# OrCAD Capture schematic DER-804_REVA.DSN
size Custom; title: DER-804; rev: RevA
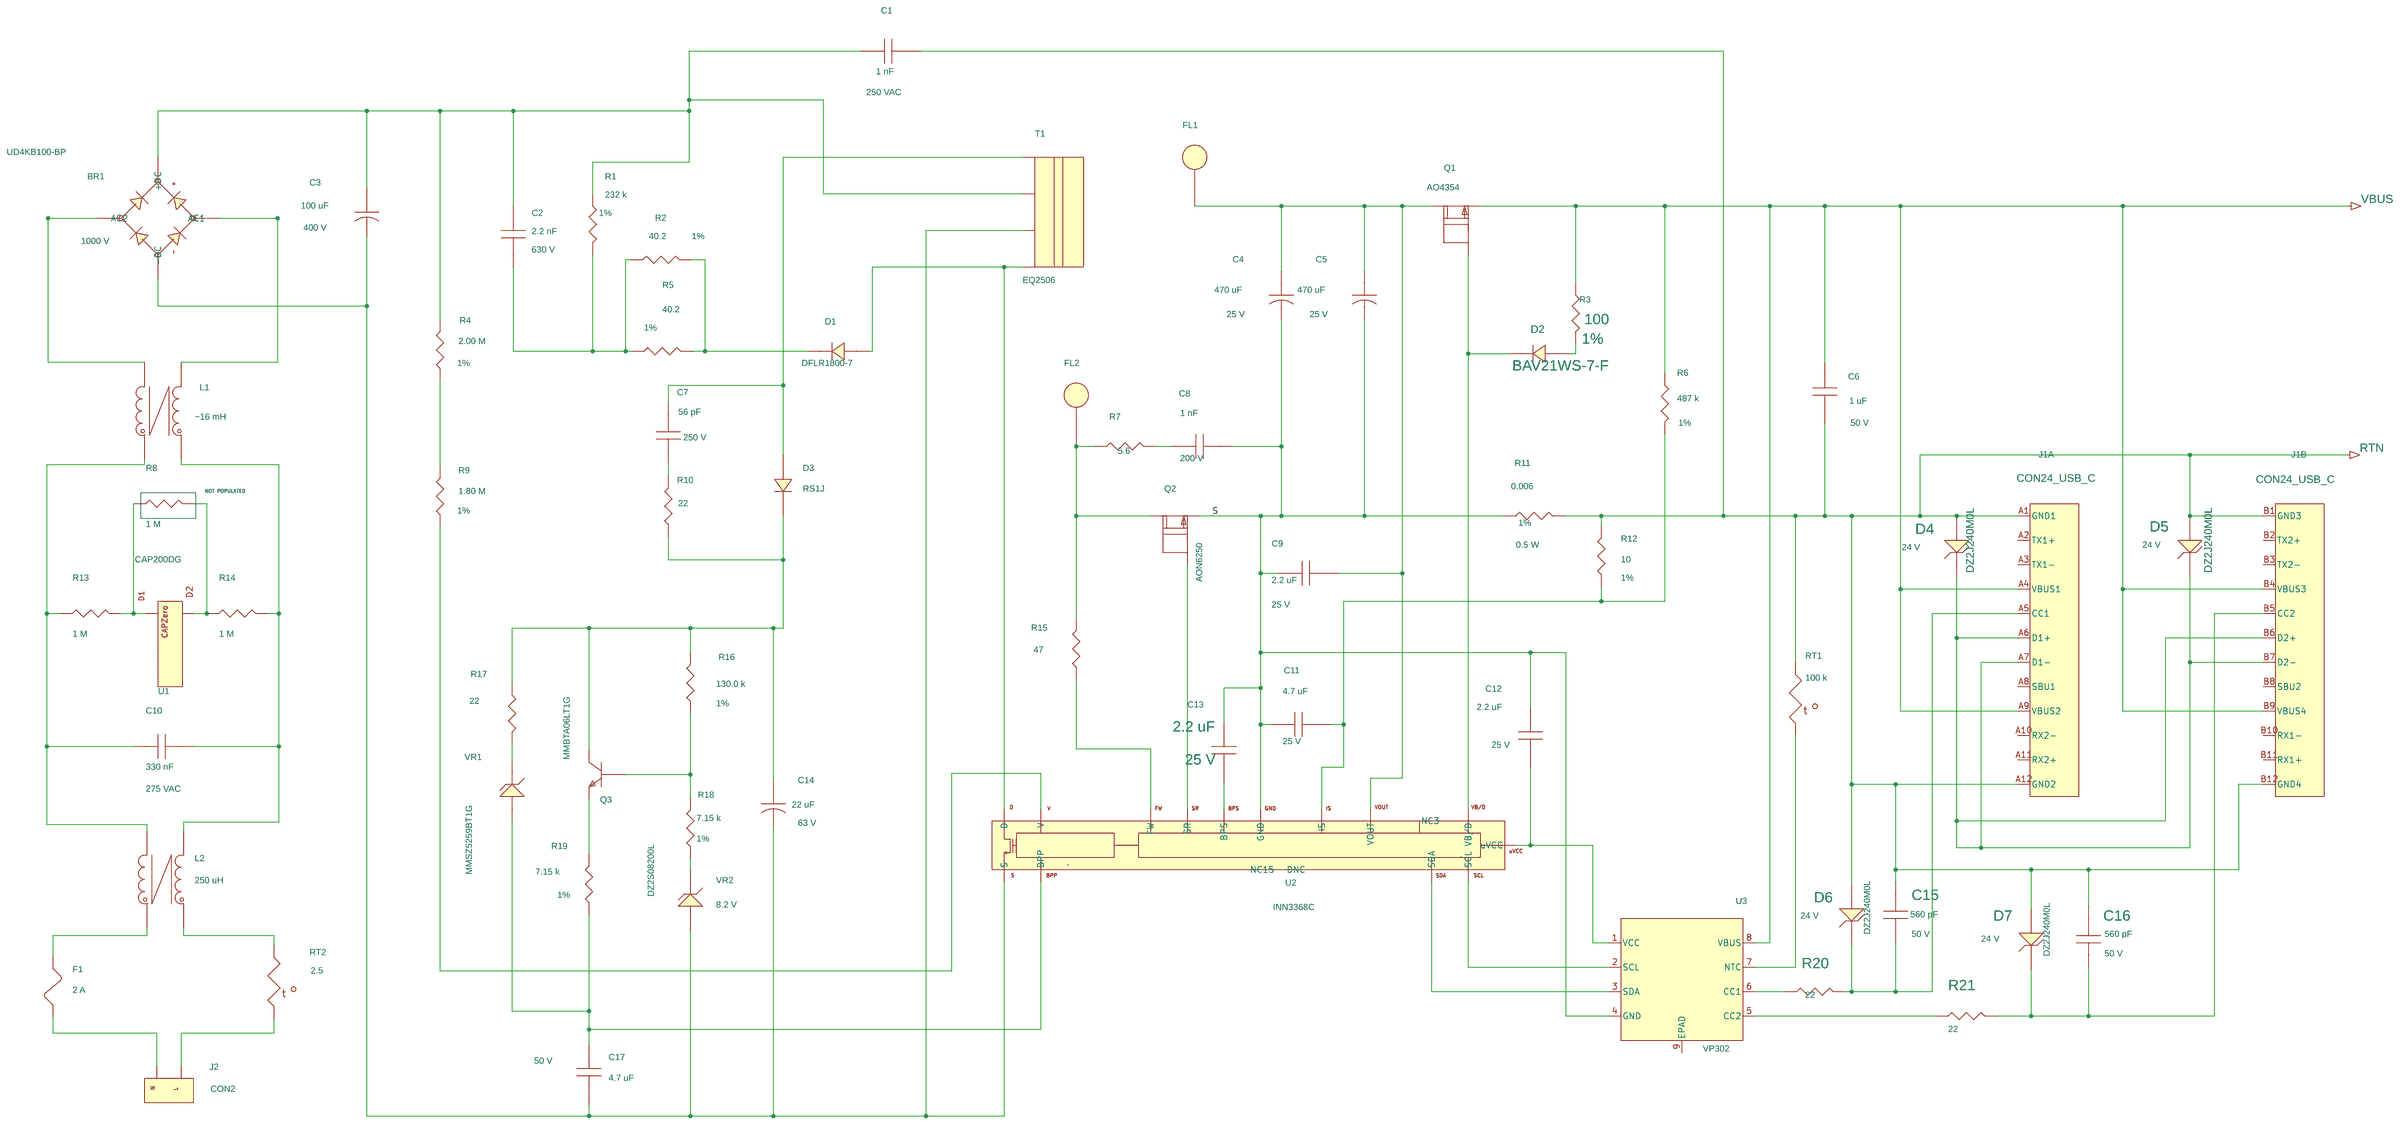
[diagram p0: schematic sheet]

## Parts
BR1  UD4KB100-BP  [pidaxbridgeD3K]
C1  1 nF  [pinpycaprad540x290ls400040]
C2  2.2 nF  [pismc1206]
C3  100 uF  [pipolcapclyd630ls300040]
C4  470 uF  [pipolcapcyld400ls200040]
C5  470 uF  [pipolcapcyld400ls200040]
C6  1 uF  [pismc0805]
C7  56 pF  [pismc0603]
C8  1 nF  [pismc0805]
C9  2.2 uF  [pismc0805]
C10  330 nF  [pinp_xcaprad15x8p5x14Hd040]
C11  4.7 uF  [pismc0805]
C12  2.2 uF  [pismc0805]
C13  2.2 uF  [pismc0805]
C14  22 uF  [pipolcapcyld250ls100030]
C15  560 pF  [pismc0603]
C16  560 pF  [pismc0603]
C17  4.7 uF  [pismc0805]
D1  DFLR1800-7  [pismddflr120012]
D2  BAV21WS-7-F  [pismsod323]
D3  RS1J  [pismdsma]
D4  DZ2J240M0L  [pi_sm_d_ssmini2p]
D5  DZ2J240M0L  [pi_sm_d_ssmini2p]
D6  DZ2J240M0L  [pi_sm_d_ssmini2p]
D7  DZ2J240M0L  [pi_sm_d_ssmini2p]
F1  2 A  [pi_rst_microfuse]
FL1  Hole_70mils  [pi_hole_70mil]
FL2  Hole_70mils  [pi_hole_70mil]
J1  CON24_USB_C  [pi_conn_USBC_Wurth]  (sections A,B)
J2  CON2  [PI_IEC320-C8]
L1  16 mH  [pi_toroid_CMC15x7_4p_V]
L2  250 uH  [pi_toroid_CMC4p_H]
Q1  AO4354  [pismso8]
Q2  AON6250  [pismpqfn5x6b]
Q3  MMBTA06LT1G  [pismsot23123_1]
R1  232 k  [pismr1206]
R2  40.2  [pismr1206]
R3  100  [pismr0603]
R4  2.00 M  [pismr1206]
R5  40.2  [pismr1206]
R6  487 k  [pismr0805]
R7  5.6  [pismr0805]
R8  1 M  [pismr1206]
R9  1.80 M  [pismr1206]
R10  22  [pismr0603]
R11  0.006  [pismr0805]
R12  10  [pismr0603]
R13  1 M  [pismr1206]
R14  1 M  [pismr1206]
R15  47  [pismr0402]
R16  130.0 k  [pismr0402]
R17  22  [pismr0603]
R18  7.15 k  [pismr0402]
R19  7.15 k  [pismr0402]
R20  22  [pismr0603]
R21  22  [pismr0603]
RT1  100 k  [pismr0603]
RT2  2.5  [pi_rad150x300ls200d030]
T1  EQ2506  [pi_bobbin_eq-2506_4p]
U1  CAP200DG  [pi_ic_smd_so8_capzero]
U2  INN3368C  [pi_ic_insop_24d]
U3  VP302  [PI_SM_DFN-8]
VR1  MMSZ5259BT1G  [pi_sm_sod-123_12]
VR2  DZ2S08200L  [pi_sm_d_ssmini2p]

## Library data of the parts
BR1 = DISCRETE_BRIDGE_+~~-: ALT_SYMBOLS: pidaxbridgeD3K_horz; Disp_Voltage: 1000 V; FPLIST: pidaxbridgeD3K,pidaxbridgeD3K_horz; Part Number: 15-01213-00
C1 = CAP_NP: ALT_SYMBOLS: pinpycaprad540x290ls400040h,pinpycaprad500x220ls400040; Disp_Voltage: 250 VAC; FPLIST: pinpycaprad540x290ls400040,pinpycaprad540x290ls400040h,pinpycaprad500x220ls400040; Part Number: 20-00375-00; Voltage: 250 VAC
C2 = CAP_NP: Disp_Voltage: 630 V; Part Number: 20-08609-00; Voltage: 630 V
C3 = CAP_POL: ALT_SYMBOLS: pipolcapclyd630ls3000401120h; COMPGROUP: 1; Disp_Voltage: 400 V; FPLIST: pipolcapclyd630ls300040,pipolcapclyd630ls3000401120h; Part Number: 20-00517-00; Voltage: 400 V
C4 C5 = CAP_POL: Disp_Voltage: 25 V; Part Number: 20-09056-00; Voltage: 25 V
C6 = CAP_NP: Disp_Voltage: 50 V; Part Number: 20-09146-00; Voltage: 50 V
C7 = CAP_NP: Disp_Voltage: 250 V; Part Number: 20-01325-00; Voltage: 250 V
C8 = CAP_NP: ALT_SYMBOLS: pismc0805_1; Disp_Voltage: 200 V; PCB Editor PCBFP: pismc0603; Part Number: 20-00737-00; Voltage: 200 V
C9 C12 C13 = CAP_NP: Disp_Voltage: 25 V; Part Number: 20-08603-00; Voltage: 25 V
C10 = CAP_NP: ALT_SYMBOLS: pinp_xcaprad15x8p5x14Hd040H; Disp_Voltage: 275 VAC; FPLIST: pinp_xcaprad15x8p5x14Hd040,pinp_xcaprad15x8p5x14Hd040H; Part Number: 20-09095-00; Voltage: 275 VAC
C11 = CAP_NP: Disp_Voltage: 25 V; Part Number: 20-09022-00; Voltage: 25 V
C14 = CAP_POL: ALT_SYMBOLS: pipolcapcyld250ls100030h; Disp_Voltage: 63 V; FPLIST: pipolcapcyld250ls100030,pipolcapcyld250ls100030h; Part Number: 20-00151-00; Voltage: 63 V
C15 C16 = CAP_NP: Disp_Voltage: 50 V; Part Number: 20-08982-00; Voltage: 50 V
C17 = CAP_NP: Disp_Voltage: 50 V; Part Number: 20-01130-00; Voltage: 50 V
D1 = DIODE: Part Number: 15-00919-00
D2 = DIODE: COMPGROUP: 1; Part Number: 15-00385-00
D3 = DIODE: Part Number: 15-00432-00
D4-D7 = DIODE_ZENER: Disp_Voltage: 24 V; Part Number: 15-01042-00
F1 = FUSE: ALT_SYMBOLS: pirstmicrofusehoz; FPLIST: pi_rst_microfuse,pirstmicrofusehoz; Part Number: 40-00021-00
FL1 FL2 = FlyingLead: Part Number: 35-00282-00
J1 = CON24_USB: Part Number: 35-00414-00
J2 = CON2_ACIN: Part Number: 35-00360-00
L1 = TORRID_4P_14_23: Part Number: 30-00463-00
L2 = TORRID_4P_12_34: ALT_SYMBOLS: pi_toroid_CMC4p_V,pi_toroid_CMC4p_V_275uH; FPLIST: pi_toroid_CMC4p_H,pi_toroid_CMC4p_V,pi_toroid_CMC4p_V_275uH; Part Number: 32-00367-00
Q1 = FET_N_SGD_123_4_5678: Part Number: 50-00260-00
Q2 = FET_N_SGD_123_4_5678: Part Number: 50-00167-00
Q3 = NPN_BEC: Part Number: 55-00072-00
R1 = R: Disp_Tol: 1%; Part Number: 05-00420-00
R2 R5 = R: Disp_Tol: 1%; Part Number: 05-00059-00
R3 = R: Disp_Tol: 1%; Part Number: 05-00982-00
R4 = R: Disp_Tol: 1%; Part Number: 05-03156-00
R6 = R: Disp_Tol: 1%; Part Number: 05-00846-00
R7 = R: Part Number: 05-01465-00
R8 R13 R14 = R: Part Number: 05-01424-00
R9 = R: Disp_Tol: 1%; Part Number: 05-03155-00
R10 R17 = R: Part Number: 05-01648-00
R11 = R: Disp_Power: 0.5 W; Disp_Tol: 1%; Part Number: 05-06516-00
R12 = R: Disp_Tol: 1%; Part Number: 05-00886-00
R15 = R: Part Number: 05-03426-00
R16 = R: Disp_Tol: 1%; Part Number: 05-06049-00
R18 R19 = R: Disp_Tol: 1%; Part Number: 05-05920-00
R20 R21 = R: COMPGROUP: 1; Part Number: 05-01648-00
RT1 = THERMISTOR: Part Number: 90-00063-00
RT2 = THERMISTOR: ALT_SYMBOLS: pirad400x300ls200040_h; FPLIST: pi_rad150x300ls200d030,pirad400x300ls200040_h; Part Number: 90-00040-00
T1 = BEQ2506_4P: Part Number: 25-01095-99
U1 = CAPZero: Part Number: 10-00958-00
U2 = DEV_InnoPro: Part Number: 10-01054-00
U3 = VP302: Part Number: 45-00495-00
VR1 = DIODE_ZENER: Part Number: 15-01100-00
VR2 = DIODE_ZENER: Disp_Voltage: 8.2 V; Part Number: 15-01006-00

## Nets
VBUS: C6.1 J1.A4(VBUS1) J1.A9(VBUS2) J1.B4(VBUS3) J1.B9(VBUS4) Q1.1(S) R3.2 R6.1 U3.8(VBUS)
NC3: U2.3(NC3)
RTN: C1.2 C6.2 C15.2 C16.2 D4.2 D5.2 D6.2 D7.2 J1.A1(GND1) J1.A12(GND2) J1.B1(GND3) J1.B12(GND4) R11.2 R12.2 RT1.1
S: C4.2 C5.2 C8.2 C9.1 C11.1 C12.1 C13.1 Q2.1(S) R11.1 U2.2(GND) U3.4(GND)
N11110714: BR1.1(+DC) C1.1 C2.1 C3.1 R1.1 R4.2 T1.2
N11110720: BR1.4(-DC) C3.2 C14.2 C17.2 T1.3 U2.16(S) VR2.2
N11111408: R4.1 R9.2
N11111567: C2.2 R1.2 R2.1 R5.1
N11111589: D1.1 R2.2 R5.2
N11116283: D1.2 T1.4 U2.24(D)
N11116458: R9.1 U2.13(V)
N12069038: R17.2 VR1.1
N12069042: Q3.1(BASE) R16.2 R18.1
N12069064: C14.1 D3.1 Q3.3(COLLECTOR) R10.1 R16.1 R17.1
N12069074: Q3.2(EMITTER) R19.1
N12069082: C17.1 R19.2 U2.14(BPP) VR1.2
N12069495: C7.2 D3.2 T1.1
N12158517: C7.1 R10.2
N12177631: C4.1 C5.1 C9.2 FL1.1 Q1.5(D) U2.10(VOUT)
N12177765: D2.1 Q1.4(G) U2.8(VB/D)
N12177789: D2.2 R3.1
N12177915: C11.2 R6.2 R12.1 U2.1(IS)
N12177961: FL2.1 Q2.5(D) R7.2 R15.1
N12178241: D4.1 D5.1 J1.A6(D1+) J1.A7(D1-) J1.B6(D2+) J1.B7(D2-)
N12178281: C15.1 D6.1 J1.A5(CC1) R20.1
N12178289: C16.1 D7.1 J1.B5(CC2) R21.1
N12178365: R15.2 U2.11(FW)
N12178457: RT1.2 U3.7(NTC)
N12178487: C13.2 U2.4(BPS)
N12178515: C12.2 U2.7(uVCC) U3.1(VCC)
N12178621: U2.6(SDA) U3.3(SDA)
N12178625: U2.5(SCL) U3.2(SCL)
N12178783: R20.2 U3.6(CC1)
N12178819: R21.2 U3.5(CC2)
N12182535: C8.1 R7.1
N12188880: Q2.4(G) U2.9(SR)
N12193829: R18.2 VR2.1
N12198989: C10.1 L1.2 L2.4 R13.1
N12198993: C10.2 L1.1 L2.2 R14.2
N12199029: R8.1 R13.2 U1.2(D1)
N12199033: R8.2 R14.1 U1.7(D2)
N12199195: F1.2 L2.3
N12199199: L2.1 RT2.1
N12199291: F1.1 J2.1
N12199295: J2.2 RT2.2
N12200850: BR1.3(AC2) L1.3
N12200878: BR1.2(AC1) L1.4

Not connected (* = marked no-connect by the designer): J1 A2(TX1+) A3(TX1-) A8(SBU1) A10(RX2-) A11(RX2+) B2(TX2+) B3(TX2-) B8(SBU2) B10(RX1-) B11(RX1+); Q1 2(S2) 3(S3) 6(D6) 7(D7) 8(D8); Q2 2(S2) 3(S3) 6(D6) 7(D7) 8(D8); U1 1(NC1) 3(NC2) 4(NC3) 5(NC4) 6(NC5) 8(NC8); U2 12(DNC) 15(NC15); U3 9(EPAD)

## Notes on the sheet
- NOT POPULATED
